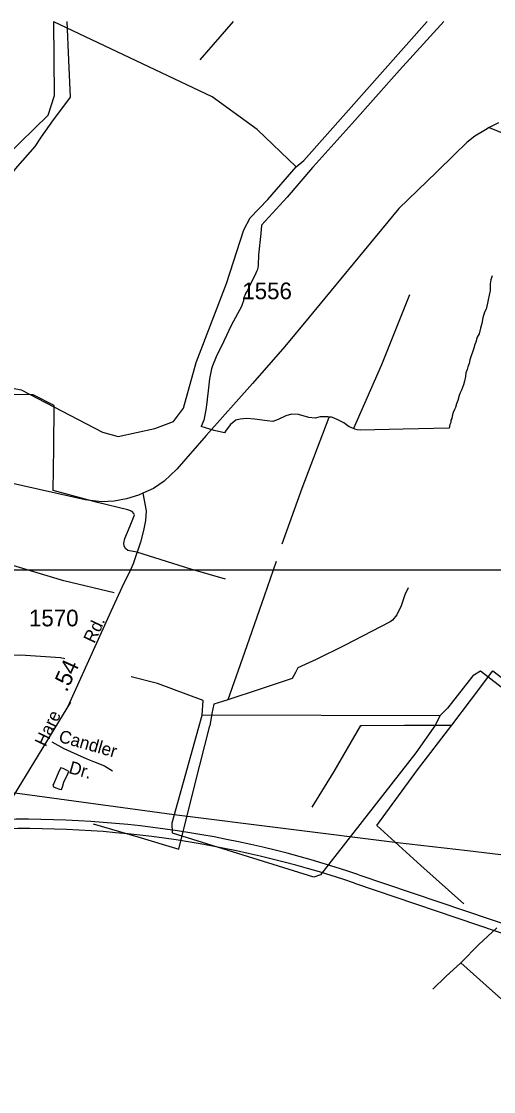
# Model space of a CAD drawing. Extents: x 2315291 to 2336543, y 597177 to 615230.
# Drawn here: x 2321750 to 2325292, y 606838 to 614871 of the extents above; entities that cross this region are included whole.
import ezdxf

# ---------------------------------------------------------------- set-up
doc = ezdxf.new("R2010")
doc.units = 0
for name, color, linetype in [('Exist Hydrographic Creek Single Shore', 7, 'Continuous'), ('Exist Hydrographic Misc Water Feature', 7, 'Continuous'), ('Exist Hydrographic Pond Under 1500 Sq Ft', 7, 'Continuous'), ('Exist Road Non-System Type 51', 7, 'Continuous'), ('Exist Road Non-System Type 51 Label', 7, 'Continuous'), ('Exist Road Primary US Attributed', 7, 'Continuous'), ('Exist Road Secondary Mileage Hundredths English Label', 7, 'Continuous'), ('Exist Road Secondary Type 51 Attributed', 7, 'Continuous'), ('Exist Road Secondary Type 51 Label', 7, 'Continuous'), ('Exist Road Secondary Type 51 Number Label', 7, 'Continuous'), ('Exist Utilities Electrical Transmission Line', 7, 'Continuous'), ('Map Preparation Inset Cut Line', 7, 'Continuous')]:
    doc.layers.add(name, color=color, linetype=linetype)

msp = doc.modelspace()

# ---------------------------------------------------------------- linework, layer by layer
at = {"layer": 'Exist Hydrographic Creek Single Shore'}
for points in [[(2320247.9, 612290.3), (2320621.2, 612293.7), (2320796.3, 612254.9), (2321106.3, 612100.1), (2321588.2, 612136), (2321747.3, 612106.4), (2322358.2, 611786.5), (2322475.3, 611755.1), (2322750.2, 611815.5), (2322891.3, 611867.1), (2322965.3, 611968.6), (2323061.3, 612310.4), (2323288.3, 612903.8), (2323417.3, 613306.1), (2323466.3, 613396.6), (2323597.3, 613533.3), (2323811.4, 613778.1)], [(2326848.4, 608712.7), (2325193.2, 609994.5), (2325135.4, 609959.4), (2324946.3, 609715.4), (2324888.3, 609657.3)]]:
    msp.add_lwpolyline(points, dxfattribs=at)
at = {"layer": 'Exist Hydrographic Misc Water Feature'}
for points in [[(2320220.3, 612330.1), (2320220.3, 612395.7), (2320465.3, 612815.8), (2320613.2, 612985.9), (2320894.3, 613154.7), (2321334.4, 613333.4), (2321441.2, 613459.1), (2321465.2, 613535.6), (2321538.2, 613709.2), (2321637.2, 613860.8), (2321950.3, 614165.6), (2321998.3, 614315.2), (2321992.2, 614866.3)], [(2322089.4, 614870.5), (2322102.5, 614580.8), (2322115.8, 614301), (2322050.8, 614214.3), (2321987.2, 614131.8), (2321898.7, 614004.8), (2321851.3, 613930.4), (2321703.6, 613764.9), (2321656.3, 613698.2), (2321605.4, 613613.8)], [(2321992.2, 614870.5), (2321992.2, 614866.3)], [(2323811.4, 613778.1), (2323517.3, 614058.4), (2323181.3, 614304), (2321992.2, 614866.3)], [(2323090.2, 614581.4), (2323341.5, 614870.5)], [(2323811.4, 613778.1), (2323869.2, 613826.4), (2324792.6, 614870.5)], [(2324918.2, 614870.5), (2324585.9, 614505.6), (2324230.5, 614103.6), (2323938.5, 613778.9)], [(2323938.5, 613778.9), (2323934.4, 613774.7), (2323742.9, 613550.8), (2323551, 613340.9), (2323545.8, 613278.8), (2323529.4, 613118.6), (2323526.4, 613038.8), (2323520.8, 613008.8), (2323513, 612994.6), (2323503.2, 612968.5), (2323473.9, 612910.4), (2323444.7, 612849.9), (2323436.3, 612835.8), (2323430.8, 612827.7), (2323424.7, 612813.6), (2323417.1, 612793.6), (2323415, 612773.7), (2323409.5, 612753.4), (2323399.8, 612731.4), (2323325, 612593), (2323268.4, 612470.1), (2323211.8, 612351.7), (2323182.5, 612285.5), (2323174.7, 612261.6), (2323162, 612187.3), (2323148.9, 612075.3), (2323147, 612057.3), (2323139.8, 612011), (2323132.2, 611954.9), (2323119.1, 611877), (2323097.4, 611830.8)], [(2325280.2, 612961.8), (2325270.5, 612929.6), (2325266.8, 612901.4), (2325266.8, 612879.5), (2325265.8, 612849.6), (2325258, 612815.5), (2325252.3, 612781.5), (2325246.7, 612755.6), (2325235.1, 612711.1), (2325223.4, 612687.3), (2325211.9, 612645.2), (2325203.9, 612603), (2325194.5, 612568.7), (2325182.8, 612524.7), (2325169, 612500.8), (2325157.5, 612462.8), (2325150, 612444.5), (2325144, 612418.6), (2325132.5, 612388.3), (2325122.7, 612360.2), (2325113, 612330), (2325109.6, 612302.1), (2325099.7, 612278), (2325093.8, 612257.8), (2325084.3, 612231.7), (2325080.4, 612205.9), (2325072.9, 612169.8), (2325065.1, 612141.7), (2325051.5, 612103.6), (2325041.9, 612083.6), (2325033.9, 612061.7), (2325022.8, 612025.2), (2325013, 611999.1), (2325005.2, 611973.1), (2324997.4, 611957.2), (2324989.4, 611934.9), (2324981.8, 611906.9), (2324977.9, 611888.8), (2324972.2, 611876.7), (2324970.3, 611860.8), (2324966.2, 611850.9), (2324964.8, 611845), (2324958.6, 611818.7), (2324614.8, 611811.2), (2324295.3, 611801.8), (2324269.3, 611805.3), (2324251, 611811.2), (2324241.2, 611815.2)], [(2324661.9, 612817.2), (2324449.9, 612293.1), (2324241.2, 611815.2)], [(2321994.4, 611988.7), (2321837.5, 612067), (2321481.8, 612069), (2321196.1, 612074.3)], [(2323281.7, 610683.3), (2323020.9, 610760.3), (2322615.9, 610886.1), (2322547.6, 610899.3), (2322530, 610913.3), (2322519.8, 610933), (2322517.3, 610954.9), (2322524.7, 610989.1), (2322565.9, 611085.5), (2322594.8, 611159.8), (2322599.1, 611167.7), (2322592.8, 611177.6), (2322581.1, 611191.5), (2322548.5, 611205.3), (2322320, 611260.8), (2321989.3, 611349.1), (2321992, 611669), (2321994.4, 611988.7)], [(2324058.3, 611901.1), (2324048.2, 611903), (2323992, 611902.1), (2323954.7, 611891.9), (2323906.3, 611897.6), (2323828.2, 611920.7), (2323776.5, 611922), (2323734.5, 611909.7), (2323674.8, 611883), (2323636.7, 611868.4), (2323592.8, 611872.2), (2323498.9, 611885.1), (2323441.1, 611890.6), (2323391, 611885.9), (2323359, 611877.4), (2323319.3, 611845.2), (2323285.8, 611802.8), (2323272.3, 611782.6), (2323196, 611799.7), (2323097.4, 611830.8)], [(2323704.8, 610949.8), (2323855.9, 611367), (2324058.3, 611901.1)], [(2324241.2, 611815.2), (2324209, 611828.6), (2324168.8, 611858.1), (2324124.3, 611879.8), (2324096.2, 611891.4), (2324076.5, 611901.2), (2324058.3, 611901.1)], [(2322445.3, 610582.5), (2322068.4, 610670.5), (2321558.9, 610824.9), (2321173.1, 610907.6), (2320850.3, 611049.4), (2320795.2, 611073)], [(2323662.1, 610817.5), (2323571.1, 610556.7), (2323423.6, 610133.1), (2323297.3, 609777.8)], [(2324651.7, 610619.9), (2324626.5, 610567.7), (2324599.2, 610483.4), (2324566, 610417), (2324532.5, 610377.1), (2324516.8, 610362.8), (2324173.1, 610185), (2323959.8, 610080.9), (2323824.5, 610019.3), (2323805, 609983.3), (2323781.4, 609939), (2323532.7, 609856.4), (2323305.3, 609779.9), (2323297.3, 609777.8)], [(2322074.8, 610085.2), (2322043.2, 610093.6), (2321744.2, 610114.3), (2320253.3, 610090), (2319979.2, 610046.1)], [(2324978.5, 609588.1), (2325126.6, 609783.6), (2325286.3, 609997.2), (2325664.8, 609705.5), (2326114.7, 609344.5), (2326489.6, 609050.5)], [(2323106.2, 609663.9), (2323113.4, 609772.6), (2322770.3, 609899.8), (2322573.7, 609952.1)], [(2323297.3, 609777.8), (2323257.5, 609765.6), (2323193.6, 609746.8)], [(2323193.6, 609746.8), (2323178.6, 609676.9), (2323163.6, 609582.6)], [(2322931.7, 608658.4), (2323050.4, 609139.8), (2323163.6, 609582.6)], [(2323931.7, 608973.1), (2324095, 609240.9), (2324297.1, 609584.8)], [(2324297.1, 609584.8), (2324303.1, 609584.7), (2324622.8, 609588.1), (2324978.5, 609588.1)], [(2324414.8, 608836.3), (2324722.2, 609253.6), (2324978.5, 609588.1)], [(2322098, 609223.5), (2322105.6, 609241.4), (2322087.7, 609251), (2322063.7, 609263.2), (2322045.5, 609268.7), (2322033.8, 609244.5), (2322018, 609210.4), (2321993.2, 609150.1), (2321986.8, 609138), (2321991.3, 609124.4), (2322007.3, 609118.3), (2322035.2, 609106.9), (2322049.4, 609104.7), (2322061.3, 609132.9), (2322068.8, 609161), (2322098, 609223.5)], [(2322287.8, 608847.8), (2322622.9, 608751.1), (2322931.7, 608658.4)], [(2325069.2, 608247.5), (2324746.2, 608534.2), (2324414.8, 608836.3)], [(2325045.8, 607803.7), (2325049.9, 607807.6), (2325180.5, 607941.2), (2325316.9, 608066.3)], [(2324836, 607607.8), (2324933, 607700.7), (2325045.8, 607803.7)], [(2326932.7, 607054.2), (2326544.3, 606942.4), (2326149.6, 606838), (2325687.4, 607233.1), (2325283.9, 607592.3), (2325045.8, 607803.7)]]:
    msp.add_lwpolyline(points, dxfattribs=at)
at = {"layer": 'Exist Hydrographic Pond Under 1500 Sq Ft'}
msp.add_line((2324888.3, 609657.3), (2323106.2, 609663.9), dxfattribs=at)
msp.add_lwpolyline([(2324888.3, 609657.3), (2324856.3, 609590.4), (2324708.3, 609381), (2323993.3, 608466), (2323944.3, 608447.6), (2322882.3, 608778.8), (2322881.3, 608854.2), (2323106.2, 609663.9)], dxfattribs=at)
at = {"layer": 'Exist Road Non-System Type 51'}
for points in [[(2325259.6, 614073.2), (2325558.1, 613951.5), (2326450.8, 613613.7), (2327039.8, 613403.5), (2327478.6, 613215.8), (2327820, 613073.2), (2328176.3, 612983.1)], [(2321977.6, 609463.6), (2322069.3, 609411.9), (2322169.3, 609366.9), (2322241, 609336.8), (2322291, 609315.2), (2322374.4, 609281.8), (2322433.5, 609244.8)]]:
    msp.add_lwpolyline(points, dxfattribs=at)
at = {"layer": 'Exist Road Primary US Attributed'}
for p, q in [((2324248.4, 608402.8), (2326243.3, 607727.1)), ((2324281.2, 608465.5), (2326291.9, 607784.6))]:
    msp.add_line(p, q, dxfattribs=at)
for centre, radius in [((2321750.2, 600992.5), 7890), ((2321761.8, 601060.6), 7751.8)]:
    msp.add_arc(centre, radius, 71.2898, 93.01588, dxfattribs=at)
at = {"layer": 'Exist Road Secondary Type 51 Attributed'}
msp.add_line((2322116.9, 609760.3), (2321080.7, 608061.5), dxfattribs=at)
for points in [[(2325328.5, 614109.4), (2325259.6, 614073.2), (2325230.1, 614057.7), (2325151.8, 614009.4), (2325090.1, 613962.6), (2324998.4, 613870.9), (2324863.4, 613739.1), (2324581.6, 613466.4), (2324319.9, 613151.1), (2323908.1, 612651.5), (2323726.4, 612429.6), (2323483, 612153.5), (2323136.3, 611763.2), (2322916.2, 611509.6), (2322819.5, 611419.5), (2322741.1, 611365.3), (2322661.1, 611328.6)], [(2322661.1, 611328.6), (2322627.8, 611313.6), (2322537.8, 611286.9), (2322446.1, 611270.2), (2322351, 611263.6), (2322227.7, 611278.6), (2321760.9, 611383.7), (2321164.1, 611518.8), (2320727.3, 611621.4), (2320450.5, 611684.8), (2320310.5, 611714.8), (2320235.5, 611729.8), (2320187.1, 611734.8), (2320133.8, 611738.2), (2320070.4, 611739.8), (2319960.4, 611703.1), (2319802, 611639.7), (2319662, 611566.3), (2319530.3, 611481.3), (2319365.3, 611356.2), (2319168.5, 611211)], [(2322661.1, 611328.6), (2322684.5, 611196.8), (2322679.5, 611123.4), (2322666.1, 611050), (2322642.8, 610961.6), (2322589.4, 610798.2), (2322567.3, 610753.3), (2322502.7, 610622.2), (2322407.7, 610413.6), (2322097.4, 609728.3)]]:
    msp.add_lwpolyline(points, dxfattribs=at)
at = {"layer": 'Exist Utilities Electrical Transmission Line'}
for points in [[(2321813.3, 609062.4), (2320886.9, 609186.2), (2319990.2, 609312.6), (2319344.2, 609400.7)], [(2329014.6, 608160.7), (2327204.2, 608382.7), (2326159.3, 608517.4), (2325096.6, 608643.9), (2324570.2, 608706.2), (2322894.9, 608916), (2321924, 609047.6), (2321813.3, 609062.4)]]:
    msp.add_lwpolyline(points, dxfattribs=at)
at = {"layer": 'Map Preparation Inset Cut Line'}
for p, q in [((2318621.3, 610753.3), (2322567.3, 610753.3)), ((2322567.3, 610753.3), (2330518.4, 610753.3))]:
    msp.add_line(p, q, dxfattribs=at)

# ---------------------------------------------------------------- texts
at = {"layer": 'Exist Road Non-System Type 51 Label'}
for s, p in [('Candler', (2322023.1, 609464.5)), ('Dr.', (2322099.2, 609230))]:
    msp.add_text(s, height=95, rotation=344.13083, dxfattribs=at).set_placement(p)
at = {"layer": 'Exist Road Secondary Mileage Hundredths English Label'}
msp.add_text('.54', height=125, rotation=65.64165, dxfattribs=at).set_placement((2322089.9, 609830.9))
at = {"layer": 'Exist Road Secondary Type 51 Label'}
for s, p in [('Rd.', (2322296.5, 610196.4)), ('Hare', (2321931.3, 609421.1))]:
    msp.add_text(s, height=95, rotation=64.77688, dxfattribs=at).set_placement(p)
at = {"layer": 'Exist Road Secondary Type 51 Number Label'}
for s, p in [('1556', (2323407.1, 612785.4)), ('1570', (2321806.7, 610330.1))]:
    msp.add_text(s, height=125, dxfattribs=at).set_placement(p)

doc.saveas('drawing.dxf')
